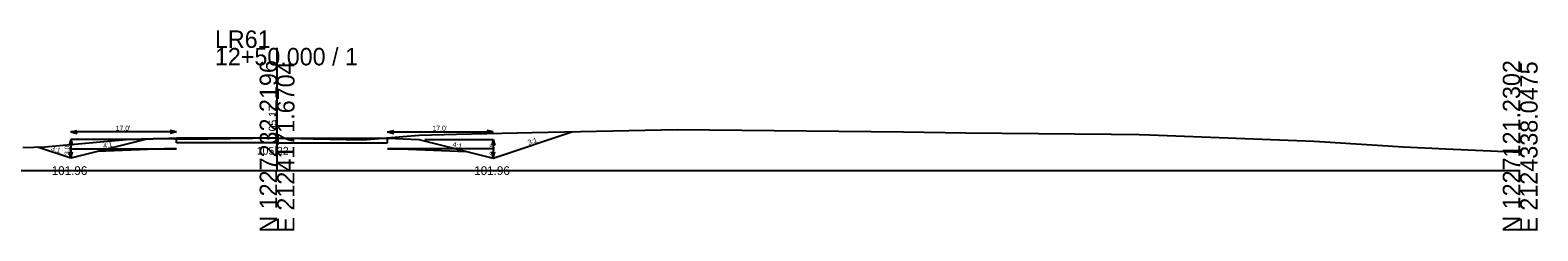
# Model space of a CAD drawing. Extents: x -26 to 1403, y -10 to 9574.
# Drawn here: x 1160.3 to 1402.8, y 2490.3 to 2522.5 of the extents above; entities that cross this region are included whole.
import ezdxf

# ---------------------------------------------------------------- set-up
doc = ezdxf.new("R2010")
doc.units = 0
for name, color, linetype in [('XS_CELL', 7, 'Continuous'), ('XS_P_FINISHED_GRADE', 7, 'Continuous'), ('XS_P_FINISHED_GRADE_ELEV_TX', 7, 'Continuous'), ('XS_P_SUBGRADE_GRANULAR', 7, 'Continuous'), ('XS_P_SUBGRADE_PAVEMENT', 7, 'Continuous'), ('XS_P_TX_CLEARZONE', 7, 'Continuous'), ('XS_P_TX_DCH', 7, 'Continuous'), ('XS_P_TX_FS_BS', 7, 'Continuous'), ('XS_X_GROUND', 7, 'Continuous'), ('XS_X_GROUND_TX', 7, 'Continuous')]:
    doc.layers.add(name, color=color, linetype=linetype)

msp = doc.modelspace()

# ---------------------------------------------------------------- linework, layer by layer
at = {"layer": 'XS_CELL'}
for p, q in [((1200, 2500), (1200, 2519.65)), ((1000, 2500), (1200, 2500)), ((1200, 2500), (1400, 2500))]:
    msp.add_line(p, q, dxfattribs=at)
at = {"layer": 'XS_P_FINISHED_GRADE'}
for p, q in [((1234.79, 2501.97), (1247.58, 2506.23)), ((1166.81, 2501.97), (1161.47, 2503.74)), ((1178.81, 2504.97), (1166.81, 2501.97)), ((1183.81, 2505.16), (1178.81, 2504.97)), ((1200, 2505.16), (1183.81, 2505.16)), ((1200, 2505.16), (1217.78, 2505.16)), ((1217.78, 2505.16), (1222.78, 2504.97)), ((1222.78, 2504.97), (1234.79, 2501.97))]:
    msp.add_line(p, q, dxfattribs=at)
at = {"layer": 'XS_P_SUBGRADE_GRANULAR'}
for p, q in [((1166.61, 2503.47), (1183.81, 2503.47)), ((1181.81, 2503.47), (1171.1, 2503.04)), ((1183.81, 2503.47), (1181.81, 2503.47)), ((1234.99, 2503.47), (1217.78, 2503.47)), ((1217.78, 2503.47), (1219.78, 2503.47)), ((1219.78, 2503.47), (1230.5, 2503.04))]:
    msp.add_line(p, q, dxfattribs=at)
at = {"layer": 'XS_P_SUBGRADE_PAVEMENT'}
for p, q in [((1183.81, 2504.41), (1183.81, 2505.16)), ((1200, 2504.41), (1183.81, 2504.41)), ((1200, 2504.41), (1217.78, 2504.41)), ((1217.78, 2504.41), (1217.78, 2505.16))]:
    msp.add_line(p, q, dxfattribs=at)
at = {"layer": 'XS_P_TX_CLEARZONE'}
for p, q in [((1166.81, 2506.16), (1167.81, 2506.41)), ((1166.81, 2506.16), (1167.81, 2505.91)), ((1183.81, 2506.16), (1166.81, 2506.16)), ((1183.81, 2506.16), (1182.81, 2506.41)), ((1183.81, 2506.16), (1182.81, 2505.91)), ((1217.78, 2506.16), (1218.78, 2506.41)), ((1217.78, 2506.16), (1218.78, 2505.91)), ((1217.78, 2506.16), (1234.79, 2506.16)), ((1234.79, 2506.16), (1233.78, 2506.41)), ((1234.79, 2506.16), (1233.78, 2505.91)), ((1166.81, 2504.97), (1166.56, 2503.97)), ((1166.81, 2504.97), (1167.06, 2503.97)), ((1166.81, 2504.97), (1166.81, 2501.97)), ((1177.81, 2504.97), (1166.81, 2504.97)), ((1223.78, 2504.97), (1234.79, 2504.97)), ((1234.79, 2504.97), (1234.53, 2503.97)), ((1234.79, 2504.97), (1234.79, 2501.97)), ((1234.79, 2504.97), (1235.04, 2503.97)), ((1166.81, 2501.97), (1166.56, 2502.97)), ((1166.81, 2501.97), (1167.06, 2502.97)), ((1234.79, 2501.97), (1234.53, 2502.97)), ((1234.79, 2501.97), (1235.04, 2502.97))]:
    msp.add_line(p, q, dxfattribs=at)
at = {"layer": 'XS_X_GROUND'}
for p, q in [((1222.85, 2505.67), (1228.87, 2505.83)), ((1228.87, 2505.83), (1241.04, 2506.1)), ((1241.04, 2506.1), (1264.39, 2506.55)), ((1264.39, 2506.55), (1300.79, 2506.16)), ((1300.79, 2506.16), (1310.83, 2506.04)), ((1310.83, 2506.04), (1334.17, 2505.8)), ((1334.17, 2505.8), (1338.71, 2505.73)), ((1159.07, 2503.68), (1162.62, 2503.77)), ((1162.62, 2503.77), (1175.73, 2504.95)), ((1175.73, 2504.95), (1176.87, 2505)), ((1176.87, 2505), (1178.17, 2505.05)), ((1178.17, 2505.05), (1179.02, 2505.07)), ((1179.02, 2505.07), (1180.04, 2505.09)), ((1180.04, 2505.09), (1180.56, 2505.1)), ((1180.56, 2505.1), (1181, 2505.11)), ((1181, 2505.11), (1181.66, 2505.1)), ((1181.66, 2505.1), (1185.29, 2505)), ((1185.29, 2505), (1196.08, 2505.15)), ((1196.08, 2505.15), (1199.8, 2505.23)), ((1199.8, 2505.23), (1205.83, 2505.08)), ((1205.83, 2505.08), (1213.81, 2504.92)), ((1213.81, 2504.92), (1222.85, 2505.67)), ((1338.71, 2505.73), (1340.43, 2505.7)), ((1340.43, 2505.7), (1366.87, 2504.68)), ((1366.87, 2504.68), (1381.21, 2503.75)), ((1381.21, 2503.75), (1388.03, 2503.46)), ((1388.03, 2503.46), (1400, 2502.91))]:
    msp.add_line(p, q, dxfattribs=at)

# ---------------------------------------------------------------- texts
at = {"layer": 'XS_CELL'}
for s, p in [('LR61', (1190, 2519.65)), ('12+50.000 / 1', (1190, 2516.85))]:
    msp.add_text(s, height=2.8, dxfattribs=at).set_placement(p)
for s, p in [('N 1227232.2196', (1200, 2490)), ('E 2124171.6704', (1202.8, 2490)), ('N 1227121.2302', (1400, 2490)), ('E 2124338.0475', (1402.8, 2490))]:
    msp.add_text(s, height=2.8, rotation=90, dxfattribs=at).set_placement(p)
at = {"layer": 'XS_P_FINISHED_GRADE_ELEV_TX'}
msp.add_text('105.17', height=1.25, rotation=90, dxfattribs=at).set_placement((1199.9, 2505.33))
at = {"layer": 'XS_P_TX_CLEARZONE'}
for p in [(1174.03, 2506.37), (1225, 2506.37)]:
    msp.add_text("17.0'", height=0.8, dxfattribs=at).set_placement(p)
for p in [(1166.61, 2502.44), (1234.99, 2502.44)]:
    msp.add_text("3.0'", height=0.8, rotation=90, dxfattribs=at).set_placement(p)
at = {"layer": 'XS_P_TX_DCH'}
for p in [(1163.74, 2499.26), (1231.72, 2499.26)]:
    msp.add_text('101.96', height=1.4, dxfattribs=at).set_placement(p)
at = {"layer": 'XS_P_TX_FS_BS'}
for s, rotation, p in [('3:1', 341.5675, (1163.56, 2503.26)), ('4:1', 14.0343, (1172.1, 2503.49)), ('4:1', 345.9663, (1228.17, 2503.82)), ('3:1', 18.4317, (1240.47, 2504.07))]:
    msp.add_text(s, height=0.8, rotation=rotation, dxfattribs=at).set_placement(p)
at = {"layer": 'XS_X_GROUND_TX'}
msp.add_text('105.22', height=1.25, rotation=360, dxfattribs=at).set_placement((1196.74, 2502.52))

doc.saveas('drawing.dxf')
